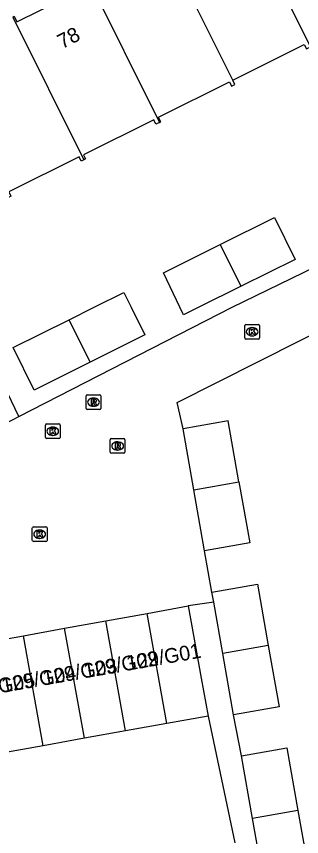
# Model space of a CAD drawing. Extents: x 157793 to 159380, y 380882 to 382313.
# Drawn here: x 158416.9 to 158436.4, y 381464 to 381519.8 of the extents above; entities that cross this region are included whole.
import ezdxf

# ---------------------------------------------------------------- set-up
doc = ezdxf.new("R2010")
doc.units = 0
for name, color, linetype in [('IMGEO_Kolk', 7, 'Continuous'), ('IMGEO_Pand', 7, 'Continuous'), ('IMGEO_Pand_nummerreeks', 7, 'Continuous'), ('IMGEO_Rijbaan_lokaal_open', 7, 'Continuous'), ('IMGEO_Rioolput', 7, 'Continuous'), ('IMGEO_Voetpad_open', 7, 'Continuous')]:
    doc.layers.add(name, color=color, linetype=linetype)

msp = doc.modelspace()

# ---------------------------------------------------------------- linework, layer by layer
at = {"layer": 'IMGEO_Kolk'}
for p, q in [((158432.483, 381497.913), (158432.483, 381498.765)), ((158432.558, 381498.839), (158433.41, 381498.839)), ((158432.971, 381498.619), (158432.996, 381498.619)), ((158433.484, 381498.765), (158433.484, 381497.913)), ((158432.994, 381498.059), (158432.969, 381498.059)), ((158433.41, 381497.839), (158432.558, 381497.839)), ((158418.911, 381491.14), (158418.911, 381491.992)), ((158418.986, 381492.066), (158419.838, 381492.066)), ((158419.399, 381491.846), (158419.424, 381491.846)), ((158419.912, 381491.992), (158419.912, 381491.14)), ((158419.422, 381491.286), (158419.397, 381491.286)), ((158419.838, 381491.066), (158418.986, 381491.066)), ((158418.024, 381484.136), (158418.024, 381484.988)), ((158418.099, 381485.062), (158418.951, 381485.062)), ((158418.512, 381484.842), (158418.537, 381484.842)), ((158419.025, 381484.988), (158419.025, 381484.136)), ((158418.951, 381484.062), (158418.099, 381484.062)), ((158418.535, 381484.282), (158418.51, 381484.282))]:
    msp.add_line(p, q, dxfattribs=at)
for points in [[(158432.483, 381497.913), (158432.483, 381498.765)], [(158432.558, 381498.839), (158433.41, 381498.839)], [(158432.804, 381498.539), (158432.927, 381498.539), (158432.927, 381498.388), (158433.057, 381498.539), (158433.221, 381498.539), (158433.075, 381498.388), (158433.228, 381498.139), (158433.076, 381498.139), (158432.991, 381498.303), (158432.927, 381498.236), (158432.927, 381498.139), (158432.804, 381498.139), (158432.804, 381498.539)], [(158433.484, 381498.765), (158433.484, 381497.913)], [(158433.41, 381497.839), (158432.558, 381497.839)], [(158418.911, 381491.14), (158418.911, 381491.992)], [(158418.986, 381492.066), (158419.838, 381492.066)], [(158419.912, 381491.992), (158419.912, 381491.14)], [(158419.232, 381491.766), (158419.355, 381491.766), (158419.355, 381491.615), (158419.485, 381491.766), (158419.649, 381491.766), (158419.503, 381491.615), (158419.656, 381491.366), (158419.504, 381491.366), (158419.419, 381491.53), (158419.355, 381491.463), (158419.355, 381491.366), (158419.232, 381491.366), (158419.232, 381491.766)], [(158419.838, 381491.066), (158418.986, 381491.066)], [(158418.024, 381484.136), (158418.024, 381484.988)], [(158418.099, 381485.062), (158418.951, 381485.062)], [(158418.345, 381484.762), (158418.468, 381484.762), (158418.468, 381484.611), (158418.598, 381484.762), (158418.762, 381484.762), (158418.616, 381484.611), (158418.769, 381484.362), (158418.617, 381484.362), (158418.532, 381484.526), (158418.468, 381484.459), (158418.468, 381484.362), (158418.345, 381484.362), (158418.345, 381484.762)], [(158419.025, 381484.988), (158419.025, 381484.136)], [(158418.951, 381484.062), (158418.099, 381484.062)]]:
    msp.add_lwpolyline(points, dxfattribs=at)
for centre, start, end in [((158432.56, 381498.763), 91.552, 178.448), ((158432.56, 381498.763), 91.552, 178.448), ((158433.408, 381498.763), 1.552, 88.448), ((158433.408, 381498.763), 1.552, 88.448), ((158432.56, 381497.915), 181.552, 268.448), ((158432.56, 381497.915), 181.552, 268.448), ((158433.408, 381497.915), 271.552, 358.448), ((158433.408, 381497.915), 271.552, 358.448), ((158418.988, 381491.99), 91.552, 178.448), ((158418.988, 381491.99), 91.552, 178.448), ((158419.836, 381491.99), 1.552, 88.448), ((158419.836, 381491.99), 1.552, 88.448), ((158418.988, 381491.142), 181.552, 268.448), ((158418.988, 381491.142), 181.552, 268.448), ((158419.836, 381491.142), 271.552, 358.448), ((158419.836, 381491.142), 271.552, 358.448), ((158418.101, 381484.986), 91.552, 178.448), ((158418.101, 381484.986), 91.552, 178.448), ((158418.949, 381484.986), 1.552, 88.448), ((158418.949, 381484.986), 1.552, 88.448), ((158418.101, 381484.138), 181.552, 268.448), ((158418.101, 381484.138), 181.552, 268.448), ((158418.949, 381484.138), 271.552, 358.448), ((158418.949, 381484.138), 271.552, 358.448)]:
    msp.add_arc(centre, 0.0765, start, end, dxfattribs=at)
for centre, major_axis, ratio, start_param, end_param in [((158432.97, 381498.339), (-0.387, 0.002), 0.722429, 4.712389, 7.853982), ((158432.995, 381498.339), (-0.39, 0.002), 0.717154, 1.570796, 4.712389), ((158419.398, 381491.566), (-0.387, 0.002), 0.722429, 4.712389, 7.853982), ((158419.423, 381491.566), (-0.39, 0.002), 0.717154, 1.570796, 4.712389), ((158418.511, 381484.562), (-0.387, 0.002), 0.722429, 4.712389, 7.853982), ((158418.536, 381484.562), (-0.39, 0.002), 0.717154, 1.570796, 4.712389)]:
    msp.add_ellipse(centre, major_axis=major_axis, ratio=ratio, start_param=start_param, end_param=end_param, dxfattribs=at)
at = {"layer": 'IMGEO_Pand'}
for points in [[(158432.111, 381527.43), (158436.947, 381517.715)], [(158431.661, 381515.448), (158427.162, 381524.49)], [(158416.695, 381519.749), (158416.791, 381519.797), (158416.978, 381519.423), (158421.751, 381521.799), (158421.569, 381522.164), (158421.839, 381522.298)], [(158421.839, 381522.298), (158426.68, 381512.572)], [(158416.695, 381519.749), (158421.532, 381510.032)], [(158431.661, 381515.448), (158436.529, 381517.871), (158436.674, 381517.579), (158436.947, 381517.715)], [(158426.68, 381512.572), (158426.776, 381512.62), (158426.62, 381512.935), (158431.438, 381515.334), (158431.584, 381515.04), (158431.809, 381515.152), (158431.661, 381515.448)], [(158426.68, 381512.572), (158426.438, 381512.452), (158426.286, 381512.758), (158421.509, 381510.38), (158421.653, 381510.092), (158421.532, 381510.032)], [(158421.532, 381510.032), (158421.358, 381509.945), (158421.211, 381510.241), (158416.419, 381507.855), (158416.567, 381507.556), (158416.394, 381507.47)], [(158430.812, 381504.271), (158434.503, 381506.108), (158435.922, 381503.258), (158432.228, 381501.427)], [(158432.228, 381501.427), (158429.35, 381500), (158428.305, 381499.482), (158428.061, 381500), (158426.954, 381502.35), (158430.812, 381504.271)], [(158432.228, 381501.427), (158430.812, 381504.271)], [(158420.533, 381499.154), (158422.233, 381500), (158424.247, 381501.002), (158424.745, 381500), (158425.68, 381498.121), (158421.967, 381496.274)], [(158421.967, 381496.274), (158418.147, 381494.373), (158416.713, 381497.254), (158420.533, 381499.154)], [(158421.967, 381496.274), (158420.533, 381499.154)], [(158432.089, 381488.13), (158431.359, 381492.278), (158428.291, 381491.739)], [(158429.021, 381487.59), (158428.291, 381491.739)], [(158429.021, 381487.59), (158432.089, 381488.13)], [(158432.089, 381488.13), (158432.819, 381483.979), (158429.751, 381483.439)], [(158429.751, 381483.439), (158429.021, 381487.59)], [(158430.249, 381480.627), (158433.344, 381481.171), (158434.08, 381476.99)], [(158430.368, 381479.951), (158430.249, 381480.627)], [(158425.831, 381479.174), (158428.637, 381479.68)], [(158428.637, 381479.68), (158429.524, 381474.76), (158429.986, 381472.195)], [(158430.985, 381476.445), (158430.368, 381479.951)], [(158423.024, 381478.668), (158425.831, 381479.174)], [(158427.18, 381471.689), (158425.831, 381479.174)], [(158420.218, 381478.162), (158423.024, 381478.668)], [(158424.374, 381471.183), (158423.024, 381478.668)], [(158417.412, 381477.656), (158420.218, 381478.162)], [(158421.568, 381470.677), (158420.218, 381478.162)], [(158414.605, 381477.15), (158417.412, 381477.656)], [(158418.761, 381470.171), (158417.412, 381477.656)], [(158434.08, 381476.99), (158430.985, 381476.445)], [(158434.08, 381476.99), (158434.815, 381472.809), (158431.72, 381472.265)], [(158431.72, 381472.265), (158430.985, 381476.445)], [(158429.986, 381472.195), (158427.18, 381471.689)], [(158424.374, 381471.183), (158421.568, 381470.677)], [(158427.18, 381471.689), (158424.374, 381471.183)], [(158421.568, 381470.677), (158418.761, 381470.171)], [(158418.761, 381470.171), (158415.955, 381469.665)], [(158432.263, 381469.486), (158435.35, 381470.029), (158436.101, 381465.761)], [(158433.014, 381465.218), (158432.263, 381469.486)], [(158436.101, 381465.761), (158433.014, 381465.218)], [(158436.101, 381465.761), (158436.813, 381461.712), (158433.726, 381461.169)], [(158433.726, 381461.169), (158433.014, 381465.218)]]:
    msp.add_lwpolyline(points, dxfattribs=at)
at = {"layer": 'IMGEO_Rijbaan_lokaal_open'}
for points in [[(158417.1, 381492.563), (158431.631, 381500), (158451.008, 381509.429)], [(158428.291, 381491.739), (158427.883, 381493.533), (158447.315, 381503.322), (158452.214, 381504.054), (158452.465, 381504.091)], [(158415.78, 381491.888), (158417.1, 381492.563)], [(158430.249, 381480.627), (158429.751, 381483.439)], [(158430.368, 381479.951), (158428.637, 381479.68)]]:
    msp.add_lwpolyline(points, dxfattribs=at)
at = {"layer": 'IMGEO_Rioolput'}
for p, q in [((158421.763, 381494.045), (158422.615, 381494.045)), ((158421.688, 381493.119), (158421.688, 381493.971)), ((158422.176, 381493.825), (158422.201, 381493.825)), ((158422.689, 381493.971), (158422.689, 381493.119)), ((158422.615, 381493.045), (158421.763, 381493.045)), ((158422.199, 381493.265), (158422.174, 381493.265)), ((158423.329, 381490.14), (158423.329, 381490.992)), ((158423.404, 381491.066), (158424.256, 381491.066)), ((158423.817, 381490.846), (158423.842, 381490.846)), ((158424.33, 381490.992), (158424.33, 381490.14)), ((158423.84, 381490.286), (158423.815, 381490.286)), ((158424.256, 381490.066), (158423.404, 381490.066))]:
    msp.add_line(p, q, dxfattribs=at)
for points in [[(158421.763, 381494.045), (158422.615, 381494.045)], [(158421.688, 381493.119), (158421.688, 381493.971)], [(158422.277, 381493.743), (158422.025, 381493.745), (158422.025, 381493.345)], [(158422.025, 381493.345), (158422.149, 381493.345), (158422.149, 381493.507), (158422.16, 381493.507)], [(158422.203, 381493.664), (158422.149, 381493.664), (158422.149, 381493.583)], [(158422.149, 381493.583), (158422.201, 381493.583)], [(158422.207, 381493.478), (158422.278, 381493.345), (158422.418, 381493.345), (158422.353, 381493.471)], [(158422.689, 381493.971), (158422.689, 381493.119)], [(158422.615, 381493.045), (158421.763, 381493.045)], [(158423.329, 381490.14), (158423.329, 381490.992)], [(158423.404, 381491.066), (158424.256, 381491.066)], [(158423.918, 381490.764), (158423.666, 381490.766), (158423.666, 381490.366)], [(158423.844, 381490.685), (158423.79, 381490.685), (158423.79, 381490.604)], [(158424.33, 381490.992), (158424.33, 381490.14)], [(158423.666, 381490.366), (158423.79, 381490.366), (158423.79, 381490.528), (158423.801, 381490.528)], [(158423.79, 381490.604), (158423.842, 381490.604)], [(158423.848, 381490.499), (158423.919, 381490.366), (158424.059, 381490.366), (158423.994, 381490.492)], [(158424.256, 381490.066), (158423.404, 381490.066)]]:
    msp.add_lwpolyline(points, dxfattribs=at)
for centre, radius, start, end in [((158421.765, 381493.969), 0.0765, 91.552, 178.448), ((158421.765, 381493.969), 0.0765, 91.552, 178.448), ((158422.613, 381493.969), 0.0765, 1.552, 88.448), ((158422.613, 381493.969), 0.0765, 1.552, 88.448), ((158422.159, 381493.454), 0.0533, 26.0293, 88.6989), ((158422.185, 381493.772), 0.19, 274.7715, 282.9687), ((158422.209, 381493.568), 0.0964, 77.0061, 93.1865), ((158422.223, 381493.625), 0.0378, 276.6634, 79.6772), ((158422.276, 381493.633), 0.109, 350.3612, 89.416), ((158422.274, 381493.633), 0.112, 277.5842, 350.9817), ((158422.258, 381493.418), 0.108, 29.5134, 73.7905), ((158421.765, 381493.121), 0.0765, 181.552, 268.448), ((158421.765, 381493.121), 0.0765, 181.552, 268.448), ((158422.613, 381493.121), 0.0765, 271.552, 358.448), ((158422.613, 381493.121), 0.0765, 271.552, 358.448), ((158423.406, 381490.99), 0.0765, 91.552, 178.448), ((158423.406, 381490.99), 0.0765, 91.552, 178.448), ((158423.85, 381490.589), 0.0964, 77.0061, 93.1865), ((158423.864, 381490.646), 0.0378, 276.6634, 79.6772), ((158423.917, 381490.654), 0.109, 350.3612, 89.416), ((158424.254, 381490.99), 0.0765, 1.552, 88.448), ((158424.254, 381490.99), 0.0765, 1.552, 88.448), ((158423.406, 381490.142), 0.0765, 181.552, 268.448), ((158423.406, 381490.142), 0.0765, 181.552, 268.448), ((158423.8, 381490.475), 0.0533, 26.0293, 88.6989), ((158423.826, 381490.793), 0.19, 274.7715, 282.9687), ((158423.915, 381490.654), 0.112, 277.5842, 350.9817), ((158423.899, 381490.439), 0.108, 29.5134, 73.7905), ((158424.254, 381490.142), 0.0765, 271.552, 358.448), ((158424.254, 381490.142), 0.0765, 271.552, 358.448)]:
    msp.add_arc(centre, radius, start, end, dxfattribs=at)
for centre, major_axis, ratio, start_param, end_param in [((158422.175, 381493.545), (-0.387, 0.002), 0.722429, 4.712389, 7.853982), ((158422.2, 381493.545), (-0.39, 0.002), 0.717154, 1.570796, 4.712389), ((158423.816, 381490.566), (-0.387, 0.002), 0.722429, 4.712389, 7.853982), ((158423.841, 381490.566), (-0.39, 0.002), 0.717154, 1.570796, 4.712389)]:
    msp.add_ellipse(centre, major_axis=major_axis, ratio=ratio, start_param=start_param, end_param=end_param, dxfattribs=at)
at = {"layer": 'IMGEO_Voetpad_open'}
for points in [[(158417.1, 381492.563), (158416.609, 381493.625), (158411.008, 381505.149)], [(158432.263, 381469.486), (158431.72, 381472.265)], [(158429.986, 381472.195), (158431.813, 381463.57)]]:
    msp.add_lwpolyline(points, dxfattribs=at)

# ---------------------------------------------------------------- texts
at = {"layer": 'IMGEO_Pand_nummerreeks'}
for s, rotation, p in [('78', 27.1638, (158420.054, 381517.556)), ('129/G01', 10.0232, (158424.525, 381475.282)), ('129/G02', 10.0232, (158421.611, 381474.766)), ('129/G04', 10.0232, (158416.018, 381473.778)), ('129/G03', 10.0232, (158418.818, 381474.273)), ('129/G05', 10.0232, (158413.219, 381473.283))]:
    msp.add_text(s, height=1, rotation=rotation, dxfattribs=at).set_placement(p)

doc.saveas('drawing.dxf')
